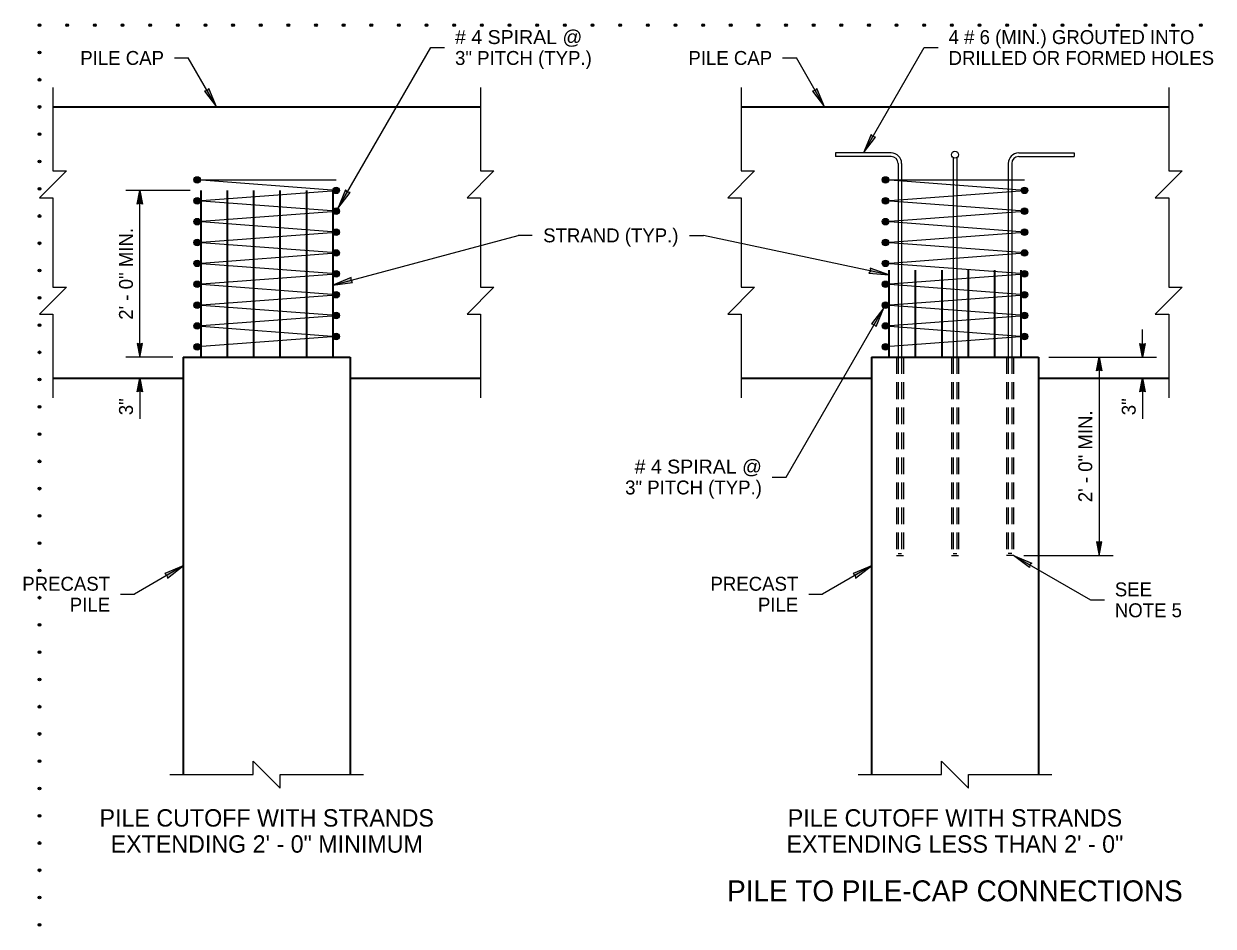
# Model space of a CAD drawing. Extents: x 99860 to 103153, y 99998 to 102077.
# Drawn here: x 99982 to 101351, y 101039 to 102077 of the extents above; entities that cross this region are included whole.
import ezdxf
from ezdxf.enums import TextEntityAlignment as Align

# ---------------------------------------------------------------- set-up
doc = ezdxf.new("R2010")
doc.units = 0
doc.header["$LTSCALE"] = 6.4
doc.header["$PDMODE"] = 32
doc.header["$PDSIZE"] = 3.2
doc.linetypes.add('MEDIUM_DASHED', pattern=[4.5, 3, -1.5])
doc.layers.add('1', color=7, linetype='Continuous')
for name, color, linetype, lineweight in [('13', 7, 'Continuous', 25), ('15', 7, 'Continuous', 13), ('2', 7, 'Continuous', 35), ('20', 7, 'Continuous', 13), ('6', 7, 'Continuous', 13)]:
    doc.layers.add(name, color=color, linetype=linetype, lineweight=lineweight)

msp = doc.modelspace()

# ---------------------------------------------------------------- hatches: boundary and pattern name
at = {"layer": '15'}
for points in [[(100203.736, 101981.017), (100194.906, 102002.28), (100192.849, 101999.873), (100189.736, 101999.295)], [(100903.574, 101981.017), (100894.744, 102002.28), (100892.687, 101999.873), (100889.574, 101999.295)], [(100948.136, 101928.019), (100962.136, 101946.297), (100959.023, 101946.875), (100956.966, 101949.283)], [(100115.487, 101885.017), (100118.571, 101869.292), (100115.487, 101870.02), (100112.403, 101869.292)], [(100343.361, 101864.264), (100357.361, 101882.542), (100354.248, 101883.12), (100352.191, 101885.528)], [(100977.486, 101787.853), (100955.778, 101795.524), (100956.19, 101792.384), (100954.535, 101789.684)], [(100337.487, 101776.081), (100360.31, 101779.106), (100358.518, 101781.716), (100358.766, 101784.873)], [(100971.611, 101749.769), (100957.612, 101731.491), (100960.725, 101730.913), (100962.781, 101728.505)], [(100115.487, 101693.017), (100118.571, 101708.742), (100115.487, 101708.014), (100112.403, 101708.742)], [(101269.487, 101693.017), (101266.403, 101708.742), (101269.487, 101708.014), (101272.571, 101708.742)], [(101219.487, 101693.017), (101222.571, 101677.292), (101219.487, 101678.02), (101216.403, 101677.292)], [(100115.487, 101669.017), (100118.571, 101653.292), (100115.487, 101654.02), (100112.403, 101653.292)], [(101269.487, 101669.017), (101272.571, 101653.292), (101269.487, 101654.02), (101266.403, 101653.292)], [(101219.486, 101465.206), (101222.57, 101480.931), (101219.486, 101480.203), (101216.402, 101480.931)], [(101120.837, 101465.206), (101142.1, 101456.376), (101139.693, 101454.319), (101139.115, 101451.206)], [(100165.486, 101453.017), (100144.223, 101444.187), (100146.63, 101442.13), (100147.207, 101439.017)], [(100957.486, 101453.017), (100936.223, 101444.187), (100938.63, 101442.13), (100939.207, 101439.017)]]:
    msp.add_hatch(color=256, dxfattribs=at).paths.add_polyline_path(points)
at = {"layer": '6'}
for points in [[(100177.736, 101897.017, 1), (100185.236, 101897.017, 1)], [(100969.736, 101897.017, 1), (100977.236, 101897.017, 1)], [(100345.236, 101885.017, 1), (100337.736, 101885.017, 1)], [(101137.236, 101885.017, 1), (101129.736, 101885.017, 1)], [(100177.736, 101873.017, 1), (100185.236, 101873.017, 1)], [(100969.736, 101873.017, 1), (100977.236, 101873.017, 1)], [(100345.236, 101861.017, 1), (100337.736, 101861.017, 1)], [(101137.236, 101861.017, 1), (101129.736, 101861.017, 1)], [(100177.736, 101849.017, 1), (100185.236, 101849.017, 1)], [(100345.236, 101837.017, 1), (100337.736, 101837.017, 1)], [(100969.736, 101849.017, 1), (100977.236, 101849.017, 1)], [(101137.236, 101837.017, 1), (101129.736, 101837.017, 1)], [(100177.736, 101825.017, 1), (100185.236, 101825.017, 1)], [(100969.736, 101825.017, 1), (100977.236, 101825.017, 1)], [(100345.236, 101813.017, 1), (100337.736, 101813.017, 1)], [(101137.236, 101813.017, 1), (101129.736, 101813.017, 1)], [(100177.736, 101801.017, 1), (100185.236, 101801.017, 1)], [(100969.736, 101801.017, 1), (100977.236, 101801.017, 1)], [(100345.236, 101789.017, 1), (100337.736, 101789.017, 1)], [(101137.236, 101789.017, 1), (101129.736, 101789.017, 1)], [(100177.736, 101777.017, 1), (100185.236, 101777.017, 1)], [(100969.736, 101777.017, 1), (100977.236, 101777.017, 1)], [(100345.236, 101765.017, 1), (100337.736, 101765.017, 1)], [(101137.236, 101765.017, 1), (101129.736, 101765.017, 1)], [(100177.736, 101753.017, 1), (100185.236, 101753.017, 1)], [(100969.736, 101753.017, 1), (100977.236, 101753.017, 1)], [(100177.736, 101729.017, 1), (100185.236, 101729.017, 1)], [(100345.236, 101741.017, 1), (100337.736, 101741.017, 1)], [(100969.736, 101729.017, 1), (100977.236, 101729.017, 1)], [(101137.236, 101741.017, 1), (101129.736, 101741.017, 1)], [(100345.236, 101717.017, 1), (100337.736, 101717.017, 1)], [(101137.236, 101717.017, 1), (101129.736, 101717.017, 1)], [(100177.736, 101705.017, 1), (100185.236, 101705.017, 1)], [(100969.736, 101705.017, 1), (100977.236, 101705.017, 1)]]:
    msp.add_hatch(color=256, dxfattribs=at).paths.add_polyline_path(points)

# ---------------------------------------------------------------- linework, layer by layer
at = {"layer": '1'}
for p in [(100000, 102075), (100031.819, 102075), (100063.637, 102075), (100095.455, 102075), (100127.273, 102075), (100159.091, 102075), (100190.909, 102075), (100222.728, 102075), (100254.546, 102075), (100286.364, 102075), (100318.182, 102075), (100350, 102075), (100381.818, 102075), (100413.637, 102075), (100445.455, 102075), (100477.273, 102075), (100509.091, 102075), (100540.909, 102075), (100572.727, 102075), (100604.546, 102075), (100636.364, 102075), (100668.182, 102075), (100700, 102075), (100731.818, 102075), (100763.636, 102075), (100795.455, 102075), (100827.273, 102075), (100859.091, 102075), (100890.909, 102075), (100922.727, 102075), (100954.545, 102075), (100986.363, 102075), (101018.182, 102075), (101050, 102075), (101081.818, 102075), (101113.636, 102075), (101145.454, 102075), (101177.272, 102075), (101209.091, 102075), (101240.909, 102075), (101272.727, 102075), (101304.545, 102075), (101336.363, 102075), (100000, 102043.644), (100000, 102012.288), (100000, 101980.932), (100000, 101949.576), (100000, 101918.22), (100000, 101886.864), (100000, 101855.508), (100000, 101824.153), (100000, 101792.797), (100000, 101761.441), (100000, 101730.085), (100000, 101698.729), (100000, 101667.373), (100000, 101636.017), (100000, 101604.661), (100000, 101573.305), (100000, 101541.949), (100000, 101510.593), (100000, 101479.237), (100000, 101447.881), (100000, 101416.525), (100000, 101385.169), (100000, 101353.814), (100000, 101322.458), (100000, 101291.102), (100000, 101259.746), (100000, 101228.39), (100000, 101197.034), (100000, 101165.678), (100000, 101134.322), (100000, 101102.966), (100000, 101071.61), (100000, 101040.254)]:
    msp.add_point(p, dxfattribs=at)
at = {"layer": '13', "lineweight": 35}
for p, q in [((100185.486, 101885.017), (100185.486, 101693.016)), ((100215.886, 101885.017), (100215.886, 101693.017)), ((100246.286, 101885.017), (100246.286, 101693.017)), ((100276.686, 101885.017), (100276.686, 101693.017)), ((100307.086, 101885.017), (100307.086, 101693.017)), ((100337.486, 101885.017), (100337.486, 101693.017)), ((100977.486, 101793.312), (100977.486, 101693.016)), ((101007.886, 101793.312), (101007.886, 101693.017)), ((101038.286, 101793.312), (101038.286, 101693.017)), ((101068.686, 101793.312), (101068.686, 101693.017)), ((101099.086, 101793.312), (101099.086, 101693.017)), ((101129.486, 101793.312), (101129.486, 101693.017))]:
    msp.add_line(p, q, dxfattribs=at)
at = {"layer": '13'}
for p, q in [((100181.486, 101729.017), (100341.486, 101717.017)), ((100973.486, 101729.017), (101133.486, 101717.017)), ((100341.486, 101717.017), (100181.486, 101705.017)), ((101133.486, 101717.017), (100973.486, 101705.017))]:
    msp.add_line(p, q, dxfattribs=at)
for points in [[(100341.486, 101885.017), (100181.486, 101897.017), (100341.486, 101897.017)], [(101133.486, 101885.017), (100973.486, 101897.017), (101133.486, 101897.017)], [(100181.486, 101729.017), (100341.486, 101741.017), (100181.486, 101753.017), (100341.486, 101765.017), (100181.486, 101777.017), (100341.486, 101789.017), (100181.486, 101801.017), (100341.486, 101813.017), (100181.486, 101825.017), (100341.486, 101837.017), (100181.486, 101849.017), (100341.486, 101861.017), (100181.486, 101873.017), (100341.486, 101885.017)], [(100973.486, 101729.017), (101133.486, 101741.017), (100973.486, 101753.017), (101133.486, 101765.017), (100973.486, 101777.017), (101133.486, 101789.017), (100973.486, 101801.017), (101133.486, 101813.017), (100973.486, 101825.017), (101133.486, 101837.017), (100973.486, 101849.017), (101133.486, 101861.017), (100973.486, 101873.017), (101133.486, 101885.017)]]:
    msp.add_lwpolyline(points, dxfattribs=at)
at = {"layer": '15'}
for p, q in [((100343.361, 101864.264), (100450.194, 102049.304)), ((100450.194, 102049.304), (100466.195, 102049.304)), ((100948.136, 101928.019), (101018.16, 102049.304)), ((101018.16, 102049.304), (101034.161, 102049.304)), ((100155.236, 102037.308), (100171.236, 102037.308)), ((100203.736, 101981.016), (100171.236, 102037.308)), ((100855.074, 102037.308), (100871.074, 102037.308)), ((100903.574, 101981.016), (100871.074, 102037.308)), ((100173.486, 101885.017), (100099.486, 101885.017)), ((100115.486, 101693.017), (100115.486, 101885.017)), ((100337.486, 101776.081), (100550.813, 101833.241)), ((100566.813, 101833.241), (100550.813, 101833.241)), ((100748.161, 101833.241), (100764.161, 101833.241)), ((100977.486, 101787.853), (100764.161, 101833.241)), ((100859.322, 101555.279), (100971.611, 101749.769)), ((101269.486, 101693.017), (101269.486, 101725.017)), ((100153.486, 101693.017), (100099.486, 101693.017)), ((101161.487, 101693.017), (101285.486, 101693.017)), ((101219.487, 101693.017), (101219.487, 101465.205)), ((100115.486, 101669.017), (100115.486, 101622.379)), ((101269.486, 101669.017), (101269.486, 101622.379)), ((100843.322, 101555.279), (100859.322, 101555.279)), ((101120.835, 101465.205), (101209.469, 101414.032)), ((101132.837, 101465.205), (101235.487, 101465.205)), ((100165.486, 101453.017), (100109.195, 101420.517)), ((100957.486, 101453.017), (100901.195, 101420.517)), ((100093.195, 101420.517), (100109.195, 101420.517)), ((100885.195, 101420.517), (100901.195, 101420.517)), ((101209.469, 101414.033), (101225.469, 101414.033))]:
    msp.add_line(p, q, dxfattribs=at)
for points in [[(100015.486, 102003.502), (100015.486, 101907.502), (100030.972, 101907.502), (100000, 101876.531), (100015.486, 101876.531), (100015.486, 101780.531)], [(100507.486, 102003.502), (100507.486, 101907.502), (100522.972, 101907.502), (100492, 101876.531), (100507.486, 101876.531), (100507.486, 101780.531)], [(100807.486, 102003.502), (100807.486, 101907.502), (100822.972, 101907.502), (100792, 101876.531), (100807.486, 101876.531), (100807.486, 101780.531)], [(101299.486, 102003.502), (101299.486, 101907.502), (101314.972, 101907.502), (101284, 101876.531), (101299.486, 101876.531), (101299.486, 101780.531)], [(100015.486, 101869.502), (100015.486, 101773.502), (100030.972, 101773.502), (100000, 101742.531), (100015.486, 101742.531), (100015.486, 101646.531)], [(100507.486, 101869.502), (100507.486, 101773.502), (100522.972, 101773.502), (100492, 101742.531), (100507.486, 101742.531), (100507.486, 101646.531)], [(100807.486, 101869.502), (100807.486, 101773.502), (100822.972, 101773.502), (100792, 101742.531), (100807.486, 101742.531), (100807.486, 101646.531)], [(101299.486, 101869.502), (101299.486, 101773.502), (101314.972, 101773.502), (101284, 101742.531), (101299.486, 101742.531), (101299.486, 101646.531)], [(100150, 101213.017), (100246, 101213.017), (100246, 101228.502), (100276.972, 101197.531), (100276.972, 101213.017), (100372.972, 101213.017)], [(100942, 101213.017), (101038, 101213.017), (101038, 101228.502), (101068.972, 101197.531), (101068.972, 101213.017), (101164.972, 101213.017)]]:
    msp.add_lwpolyline(points, dxfattribs=at)
for points in [[(100203.736, 101981.017), (100194.906, 102002.28), (100192.849, 101999.873), (100189.736, 101999.295)], [(100903.574, 101981.017), (100894.744, 102002.28), (100892.687, 101999.873), (100889.574, 101999.295)], [(100948.136, 101928.019), (100962.136, 101946.297), (100959.023, 101946.875), (100956.966, 101949.283)], [(100115.487, 101885.017), (100118.571, 101869.292), (100115.487, 101870.02), (100112.403, 101869.292)], [(100343.361, 101864.264), (100357.361, 101882.542), (100354.248, 101883.12), (100352.191, 101885.528)], [(100977.486, 101787.853), (100955.778, 101795.524), (100956.19, 101792.384), (100954.535, 101789.684)], [(100337.487, 101776.081), (100360.31, 101779.106), (100358.518, 101781.716), (100358.766, 101784.873)], [(100971.611, 101749.769), (100957.612, 101731.491), (100960.725, 101730.913), (100962.781, 101728.505)], [(100115.487, 101693.017), (100118.571, 101708.742), (100115.487, 101708.014), (100112.403, 101708.742)], [(101269.487, 101693.017), (101266.403, 101708.742), (101269.487, 101708.014), (101272.571, 101708.742)], [(101219.487, 101693.017), (101222.571, 101677.292), (101219.487, 101678.02), (101216.403, 101677.292)], [(100115.487, 101669.017), (100118.571, 101653.292), (100115.487, 101654.02), (100112.403, 101653.292)], [(101269.487, 101669.017), (101272.571, 101653.292), (101269.487, 101654.02), (101266.403, 101653.292)], [(101219.486, 101465.206), (101222.57, 101480.931), (101219.486, 101480.203), (101216.402, 101480.931)], [(101120.837, 101465.206), (101142.1, 101456.376), (101139.693, 101454.319), (101139.115, 101451.206)], [(100165.486, 101453.017), (100144.223, 101444.187), (100146.63, 101442.13), (100147.207, 101439.017)], [(100957.486, 101453.017), (100936.223, 101444.187), (100938.63, 101442.13), (100939.207, 101439.017)]]:
    msp.add_lwpolyline(points, close=True, dxfattribs=at)
at = {"layer": '2'}
for p, q in [((100015.486, 101981.017), (100507.486, 101981.017)), ((100807.486, 101981.017), (101299.486, 101981.017)), ((100165.486, 101693.017), (100165.486, 101213.017)), ((100165.486, 101693.017), (100357.486, 101693.017)), ((100357.486, 101693.017), (100357.486, 101213.017)), ((100957.486, 101693.017), (100957.486, 101213.017)), ((100957.486, 101693.017), (101149.486, 101693.017)), ((101149.486, 101693.017), (101149.486, 101213.017)), ((100015.486, 101669.017), (100165.486, 101669.017)), ((100357.486, 101669.017), (100507.486, 101669.017)), ((100807.486, 101669.017), (100957.486, 101669.017)), ((101149.486, 101669.017), (101299.486, 101669.017))]:
    msp.add_line(p, q, dxfattribs=at)
at = {"layer": '6'}
for p, q in [((100980.136, 101924.019), (100916.136, 101924.019)), ((101126.837, 101924.019), (101190.837, 101924.019)), ((100988.136, 101916.019), (100988.136, 101693.017)), ((100992.136, 101916.019), (100992.136, 101693.017)), ((101051.486, 101922.555), (101051.486, 101693.017)), ((101055.486, 101922.555), (101055.486, 101693.017)), ((101114.837, 101916.019), (101114.837, 101693.017)), ((101118.837, 101916.019), (101118.837, 101693.017))]:
    msp.add_line(p, q, dxfattribs=at)
at = {"layer": '6', "linetype": 'MEDIUM_DASHED'}
for p, q in [((100986.136, 101693.017), (100986.136, 101465.205)), ((100988.136, 101693.017), (100988.136, 101467.205)), ((100992.136, 101693.017), (100992.136, 101467.205)), ((100994.136, 101693.017), (100994.136, 101465.205)), ((101049.486, 101693.017), (101049.486, 101465.205)), ((101051.486, 101693.017), (101051.486, 101467.205)), ((101055.486, 101693.017), (101055.486, 101467.205)), ((101057.486, 101693.017), (101057.486, 101465.205)), ((101112.837, 101693.017), (101112.837, 101465.205)), ((101114.837, 101693.017), (101114.837, 101467.205)), ((101118.837, 101693.017), (101118.837, 101467.205)), ((101120.837, 101693.017), (101120.837, 101465.205)), ((100986.136, 101465.205), (100994.136, 101465.205)), ((100988.136, 101467.205), (100992.136, 101467.205)), ((101049.486, 101465.205), (101057.486, 101465.205)), ((101051.486, 101467.205), (101055.486, 101467.205)), ((101120.837, 101465.205), (101112.837, 101465.205)), ((101118.837, 101467.205), (101114.837, 101467.205))]:
    msp.add_line(p, q, dxfattribs=at)
at = {"layer": '6'}
for points in [[(100980.136, 101928.019), (100916.136, 101928.019), (100916.136, 101924.019)], [(101126.837, 101928.019), (101190.837, 101928.019), (101190.837, 101924.019)]]:
    msp.add_lwpolyline(points, dxfattribs=at)
for centre, radius in [((101053.486, 101926.019), 4), ((100181.486, 101897.017), 3.75), ((100973.486, 101897.017), 3.75), ((100341.486, 101885.017), 3.75), ((101133.486, 101885.017), 3.75), ((100181.486, 101873.017), 3.75), ((100973.486, 101873.017), 3.75), ((100341.486, 101861.017), 3.75), ((101133.486, 101861.017), 3.75), ((100181.486, 101849.017), 3.75), ((100341.486, 101837.017), 3.75), ((100973.486, 101849.017), 3.75), ((101133.486, 101837.017), 3.75), ((100181.486, 101825.017), 3.75), ((100973.486, 101825.017), 3.75), ((100341.486, 101813.017), 3.75), ((101133.486, 101813.017), 3.75), ((100181.486, 101801.017), 3.75), ((100973.486, 101801.017), 3.75), ((100341.486, 101789.017), 3.75), ((101133.486, 101789.017), 3.75), ((100181.486, 101777.017), 3.75), ((100973.486, 101777.017), 3.75), ((100341.486, 101765.017), 3.75), ((101133.486, 101765.017), 3.75), ((100181.486, 101753.017), 3.75), ((100973.486, 101753.017), 3.75), ((100181.486, 101729.017), 3.75), ((100341.486, 101741.017), 3.75), ((100973.486, 101729.017), 3.75), ((101133.486, 101741.017), 3.75), ((100341.486, 101717.017), 3.75), ((101133.486, 101717.017), 3.75), ((100181.486, 101705.017), 3.75), ((100973.486, 101705.017), 3.75)]:
    msp.add_circle(centre, radius, dxfattribs=at)
for centre, radius, start, end in [((100980.136, 101916.019), 12, 0, 90), ((100980.136, 101916.019), 8, 0, 90), ((101126.837, 101916.019), 12, 90, 180), ((101126.837, 101916.019), 8, 90, 180)]:
    msp.add_arc(centre, radius, start, end, dxfattribs=at)

# ---------------------------------------------------------------- texts
at = {"layer": '20', "width": 1.05}
msp.add_text('# 4 SPIRAL @', height=16, dxfattribs=at).set_placement((100478.206, 102053.312))
at = {"layer": '20'}
for s, p in [('4 # 6 (MIN.) GROUTED INTO', (101046.17, 102053.312)), ('3" PITCH (TYP.)', (100478.206, 102029.311)), ('DRILLED OR FORMED HOLES', (101046.17, 102029.311)), ('SEE', (101237.473, 101418.037)), ('NOTE 5', (101237.473, 101394.036))]:
    msp.add_text(s, height=16, dxfattribs=at).set_placement(p)
for s, p in [('PILE CAP', (100143.237, 102029.311)), ('PILE CAP', (100843.076, 102029.311)), ('3" PITCH (TYP.)', (100831.326, 101535.285)), ('PRECAST', (100081.198, 101424.523)), ('PRECAST', (100873.198, 101424.523)), ('PILE', (100081.198, 101400.522)), ('PILE', (100873.198, 101400.522))]:
    msp.add_text(s, height=16, dxfattribs=at).set_placement(p, align=Align.RIGHT)
for s, height, p in [('STRAND (TYP.)', 16, (100657.487, 101825.243)), ('PILE CUTOFF WITH STRANDS', 20, (100261.487, 101153.218)), ('PILE CUTOFF WITH STRANDS', 20, (101053.487, 101153.218)), ('EXTENDING 2\' - 0" MINIMUM', 20, (100261.487, 101123.218)), ('EXTENDING LESS THAN 2\' - 0"', 20, (101053.487, 101123.218)), ('PILE TO PILE-CAP CONNECTIONS', 24, (101053.487, 101067.345))]:
    msp.add_text(s, height=height, dxfattribs=at).set_placement(p, align=Align.CENTER)
for s, p in [('2\' - 0" MIN.', (100107.488, 101789.019)), ('3"', (100107.488, 101636.122)), ('3"', (101261.489, 101636.122)), ('2\' - 0" MIN.', (101211.49, 101579.111))]:
    msp.add_text(s, height=16, rotation=90, dxfattribs=at).set_placement(p, align=Align.CENTER)
at = {"layer": '20', "width": 1.05}
msp.add_text('# 4 SPIRAL @', height=16, dxfattribs=at).set_placement((100831.326, 101559.286), align=Align.RIGHT)

doc.saveas('drawing.dxf')
